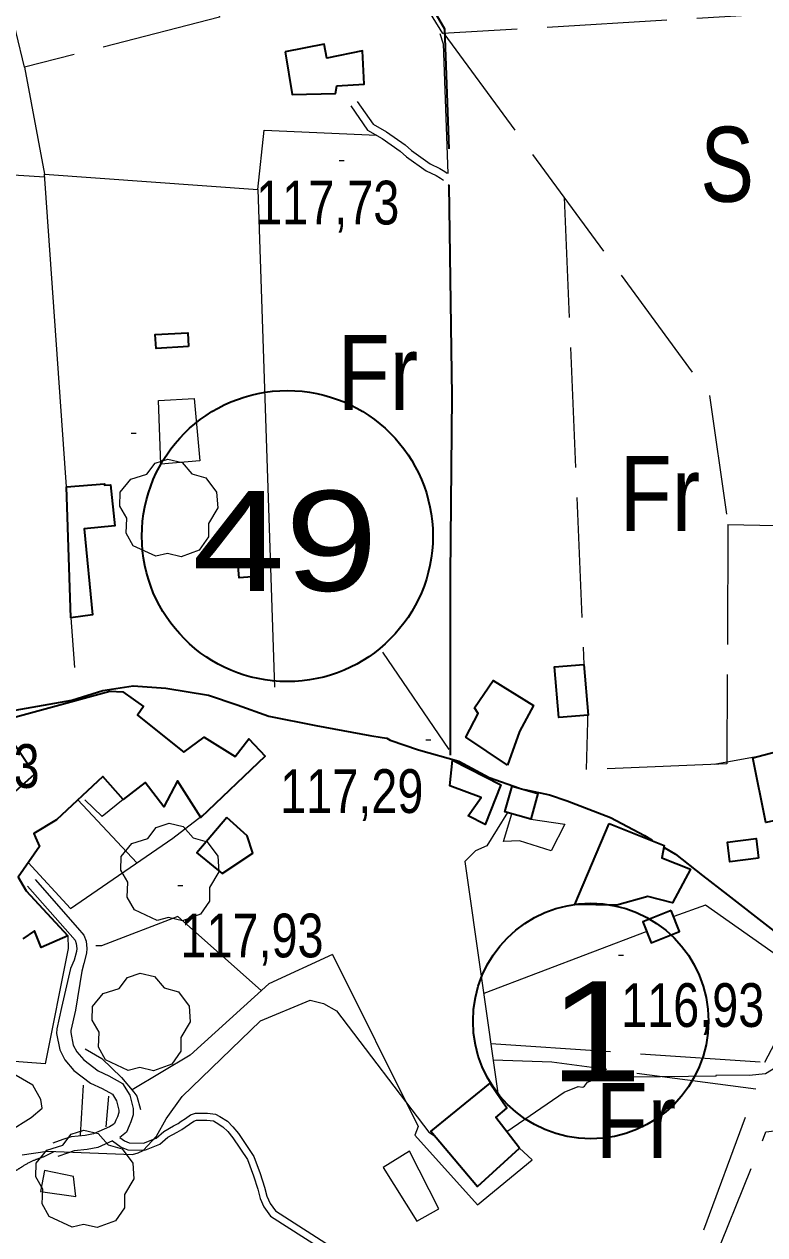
# Model space of a CAD drawing. Extents: x 483840 to 488445, y 4386047 to 4389027.
# Drawn here: x 486641.4 to 486789.5, y 4387167.2 to 4387409.3 of the extents above; entities that cross this region are included whole.
import ezdxf
from ezdxf.enums import TextEntityAlignment as Align

# ---------------------------------------------------------------- set-up
doc = ezdxf.new("R2010")
doc.units = 0
doc.header["$LTSCALE"] = 4
doc.linetypes.add('LONG_DASHED', pattern=[7.5, 6, -1.5])
doc.linetypes.add('MEDIUM_DASHED', pattern=[4.5, 3, -1.5])
for name, color, linetype, lineweight in [('13', 7, 'Continuous', 25), ('21', 7, 'Continuous', 25), ('25', 7, 'LONG_DASHED', 25), ('29', 7, 'Continuous', 13), ('38', 7, 'Continuous', 25), ('47', 7, 'Continuous', 35), ('51', 7, 'Continuous', 13), ('6', 7, 'Continuous', 35), ('7', 7, 'Continuous', 13), ('9', 7, 'Continuous', 13)]:
    doc.layers.add(name, color=color, linetype=linetype, lineweight=lineweight)
doc.layers.add('31', color=7, linetype='Continuous')

msp = doc.modelspace()

# ---------------------------------------------------------------- linework, layer by layer
at = {"layer": '21'}
for points in [[(486675.39, 4387334.46), (486676.49, 4387321.98), (486668.75, 4387321.35), (486668.26, 4387334.03)], [(486742.69, 4387250.35), (486749.51, 4387249.35), (486746.8, 4387243.99), (486740.46, 4387246.03), (486737.23, 4387245.85), (486738.94, 4387251.41)], [(486713.18, 4387180.69), (486719.93, 4387169.94), (486724.32, 4387172.43), (486718.48, 4387183.99)], [(486651.25, 4387178.88), (486645.49, 4387180.08), (486644.68, 4387175.89), (486651.72, 4387174.89)]]:
    msp.add_lwpolyline(points, close=True, dxfattribs=at)
at = {"layer": '25'}
for p, q in [((486641.45, 4387400.67), (486645.49, 4387379.31)), ((486749.4, 4387374.62), (486753.34, 4387281.26)), ((486779.41, 4387261.32), (486788.5, 4387262.98))]:
    msp.add_line(p, q, dxfattribs=at)
for points in [[(486668.94, 4387470.89), (486680.46, 4387410.7), (486641.45, 4387400.67), (486622.19, 4387482.1)], [(486645.54, 4387378.72), (486599.15, 4387381.62), (486587.21, 4387477.67)], [(486814.89, 4387349.55), (486799.86, 4387411.84), (486725.13, 4387407.43), (486717.36, 4387420.22)], [(486725.29, 4387407.45), (486778.42, 4387335.08), (486782.11, 4387309.29), (486810.46, 4387308.66)], [(486688.14, 4387376.22), (486689.37, 4387388.13), (486711.93, 4387387.08)], [(486782.11, 4387309.29), (486781.95, 4387261.42), (486753.79, 4387260.25)], [(486688.81, 4387216.06), (486672.11, 4387230.88), (486656.86, 4387225.02), (486655.75, 4387225.02)], [(486703.06, 4387223.31), (486690.3, 4387217.41), (486674.56, 4387203.15), (486662.97, 4387196.2)], [(486734.71, 4387205.52), (486789.5, 4387201.73), (486798.21, 4387218.42)], [(486607.56, 4387172.52), (486626.38, 4387181.41), (486631.95, 4387182.83), (486636.04, 4387185.55), (486638.32, 4387187.92), (486642.79, 4387190.7), (486644.99, 4387192.55), (486644.72, 4387194.28), (486643.11, 4387197.15), (486639.76, 4387199.08), (486634.67, 4387200.2), (486631.88, 4387199.34), (486628.62, 4387196.91), (486625.36, 4387194.55), (486620.2, 4387190.13), (486615.21, 4387187.5), (486609.43, 4387187.35), (486607.1, 4387187.39), (486600.63, 4387186.38)], [(486725.97, 4387152.98), (486730.79, 4387147.42), (486766.93, 4387140.08), (486787.69, 4387196.36), (486746.95, 4387201.74), (486735.2, 4387202.13)], [(486609.56, 4387156.72), (486630.57, 4387160.04), (486653.72, 4387157.46), (486670.08, 4387152.42), (486684.83, 4387149.81), (486683.34, 4387124.84), (486719.13, 4387119.6), (486726.62, 4387144.56), (486749.13, 4387138.98), (486759.81, 4387135.68), (486764.23, 4387135.46), (486768.88, 4387135.32), (486777.77, 4387158.23), (486789.75, 4387187.85), (486800.8, 4387189.1)]]:
    msp.add_lwpolyline(points, dxfattribs=at)
at = {"layer": '29'}
for points in [[(486667.74, 4387302.9), (486663.2, 4387305.02), (486661.79, 4387307.56), (486661.89, 4387310.54), (486660.52, 4387312.95), (486660.56, 4387315.7), (486662.72, 4387318.3), (486665.91, 4387319.3), (486667.56, 4387321.49), (486670.13, 4387322.32), (486672.99, 4387321.67), (486674.94, 4387319.4), (486677.75, 4387318.58), (486679.88, 4387315.73), (486680.12, 4387312.6), (486678.24, 4387309.45), (486678.24, 4387306.77), (486676.42, 4387304.16), (486672.8, 4387302.82), (486670.03, 4387303.45)], [(486667.97, 4387230.11), (486663.43, 4387232.23), (486662.02, 4387234.77), (486662.12, 4387237.75), (486660.75, 4387240.16), (486660.79, 4387242.91), (486662.95, 4387245.51), (486666.14, 4387246.51), (486667.79, 4387248.7), (486670.36, 4387249.53), (486673.22, 4387248.88), (486675.17, 4387246.61), (486677.98, 4387245.79), (486680.11, 4387242.94), (486680.35, 4387239.81), (486678.47, 4387236.66), (486678.47, 4387233.98), (486676.65, 4387231.37), (486673.03, 4387230.03), (486670.26, 4387230.66)], [(486662.22, 4387200.11), (486657.68, 4387202.23), (486656.27, 4387204.77), (486656.37, 4387207.75), (486655, 4387210.16), (486655.04, 4387212.91), (486657.2, 4387215.51), (486660.39, 4387216.51), (486662.04, 4387218.7), (486664.61, 4387219.53), (486667.47, 4387218.88), (486669.42, 4387216.61), (486672.23, 4387215.79), (486674.36, 4387212.94), (486674.6, 4387209.81), (486672.72, 4387206.66), (486672.72, 4387203.98), (486670.9, 4387201.37), (486667.28, 4387200.03), (486664.51, 4387200.66)], [(486650.96, 4387168.75), (486646.42, 4387170.87), (486645.01, 4387173.41), (486645.11, 4387176.39), (486643.74, 4387178.8), (486643.78, 4387181.55), (486645.94, 4387184.15), (486649.13, 4387185.15), (486650.78, 4387187.34), (486653.35, 4387188.17), (486656.21, 4387187.52), (486658.16, 4387185.25), (486660.97, 4387184.43), (486663.1, 4387181.58), (486663.34, 4387178.45), (486661.46, 4387175.3), (486661.46, 4387172.62), (486659.64, 4387170.01), (486656.02, 4387168.67), (486653.25, 4387169.3)]]:
    msp.add_lwpolyline(points, close=True, dxfattribs=at)
at = {"layer": '38'}
for points in [[(486707.99, 4387393.86), (486711.17, 4387389.28), (486713.83, 4387387.76), (486717.57, 4387385.16), (486718.83, 4387384.02), (486722.57, 4387381.35), (486724.54, 4387380.44), (486725.51, 4387379.85), (486726.01, 4387379.51)], [(486642.09, 4387236.92), (486650.58, 4387227.28), (486651.57, 4387226.12), (486651.81, 4387225.5), (486651.92, 4387224.47), (486651.86, 4387223.91), (486651.42, 4387222.12), (486650.68, 4387220.49)], [(486643.59, 4387238.25), (486652.09, 4387228.59), (486653.31, 4387227.17), (486653.78, 4387225.98), (486653.93, 4387224.47), (486653.83, 4387223.56), (486653.32, 4387221.46), (486652.92, 4387219.98)], [(486650.68, 4387220.49), (486648.89, 4387212.68), (486647.91, 4387208.41), (486647.89, 4387207.46), (486648.5, 4387204.21), (486649.54, 4387202.24), (486651.35, 4387200.12), (486654.68, 4387197.59), (486657.01, 4387196.47), (486659.06, 4387195.34), (486659.88, 4387194.05), (486660.35, 4387192.16), (486660.35, 4387191.71), (486660.04, 4387190.83), (486659.74, 4387190.13), (486659.48, 4387189.51), (486659.13, 4387189.21), (486658.46, 4387188.85), (486655.24, 4387187.41), (486653.57, 4387187.1), (486650.78, 4387186.83), (486649.11, 4387186.27), (486647.13, 4387185.55)], [(486652.92, 4387219.98), (486651.69, 4387212.13), (486650.75, 4387208.06), (486650.75, 4387207.7), (486651.22, 4387205.16), (486651.91, 4387203.85), (486653.31, 4387202.21), (486656.18, 4387200.03), (486658.31, 4387199), (486661.08, 4387197.48), (486662.53, 4387195.19), (486663.21, 4387192.49), (486663.19, 4387191.21), (486662.7, 4387189.8), (486662.36, 4387189.01), (486661.84, 4387187.78), (486660.55, 4387186.67)], [(486660.55, 4387186.67), (486661.47, 4387186.02), (486662.42, 4387185.62), (486665.26, 4387185.59), (486667.78, 4387186.59), (486669.33, 4387187.89), (486671.27, 4387189.02), (486672.17, 4387189.52), (486672.82, 4387189.94), (486673.65, 4387190.52), (486674.63, 4387191.23), (486675.64, 4387191.59), (486678.03, 4387191.55), (486679.66, 4387191.37), (486680.54, 4387190.91), (486682.03, 4387189.94), (486683.13, 4387188.82), (486684.26, 4387187.48), (486687.34, 4387182.92), (486688.59, 4387179.52), (486689.47, 4387176.78), (486689.95, 4387174.93), (486690.57, 4387173.52), (486691.64, 4387172), (486703.59, 4387164.38)], [(486659.05, 4387186), (486656.1, 4387184.68), (486653.97, 4387184.28), (486651.38, 4387184.03), (486650.06, 4387183.59), (486648.12, 4387182.87)]]:
    msp.add_lwpolyline(points, dxfattribs=at)
at = {"layer": '38', "linetype": 'MEDIUM_DASHED'}
for points in [[(486706.69, 4387392.96), (486710.07, 4387388.09), (486712.98, 4387386.42), (486716.58, 4387383.92), (486717.83, 4387382.78), (486721.77, 4387379.97), (486723.8, 4387379.03), (486724.65, 4387378.52), (486725.24, 4387378.11)], [(486659.05, 4387186), (486660.79, 4387184.78), (486662.12, 4387184.22), (486665.52, 4387184.18), (486668.51, 4387185.36), (486670.14, 4387186.73), (486671.97, 4387187.79), (486672.89, 4387188.31), (486673.61, 4387188.77), (486674.47, 4387189.38), (486675.29, 4387189.97), (486675.87, 4387190.18), (486677.94, 4387190.15), (486679.24, 4387190), (486679.82, 4387189.7), (486681.13, 4387188.85), (486682.09, 4387187.87), (486683.14, 4387186.62), (486686.08, 4387182.27), (486687.26, 4387179.06), (486688.12, 4387176.39), (486688.62, 4387174.47), (486689.34, 4387172.83), (486690.64, 4387170.96), (486702.83, 4387163.19)]]:
    msp.add_lwpolyline(points, dxfattribs=at)
at = {"layer": '38', "linetype": 'LONG_DASHED'}
msp.add_spline([(486607.2, 4387168.1), (486614.36, 4387170.4), (486621.75, 4387173.07), (486631.7, 4387176.15), (486637.52, 4387178.85), (486639.86, 4387180.16), (486641.15, 4387180.97), (486643.34, 4387182.14), (486645.23, 4387182.86), (486647.41, 4387183.91)], degree=3, dxfattribs=at)
at = {"layer": '47'}
for points in [[(486693.57, 4387403.76), (486695.02, 4387395.26), (486703.65, 4387395.43), (486703.9, 4387397), (486709.38, 4387397.3), (486709.03, 4387403.98), (486701.95, 4387402.51), (486701.39, 4387405.29)], [(486674.26, 4387344.83), (486667.77, 4387344.47), (486667.62, 4387347.25), (486674.11, 4387347.61)], [(486650.75, 4387290.61), (486649.85, 4387316.81), (486657.48, 4387317.36), (486657.49, 4387317.1), (486658.65, 4387317.22), (486659.5, 4387308.99), (486653.39, 4387308.4), (486655.04, 4387291.23)], [(486688.69, 4387298.92), (486684.37, 4387298.62), (486684.15, 4387301.69), (486688.47, 4387301.99)], [(486753.34, 4387281.26), (486754.19, 4387271.17), (486748.31, 4387270.68), (486747.46, 4387280.77)], [(486738.05, 4387261.15), (486729.72, 4387266.75), (486732.19, 4387271.44), (486731.46, 4387272.57), (486735.21, 4387278.07), (486743.24, 4387273.08), (486740.47, 4387267.87)], [(486806.59, 4387253.19), (486789.73, 4387249.68), (486787.14, 4387262.62), (486795.2, 4387264.76), (486809.98, 4387264.77), (486817.05, 4387266.02), (486818.71, 4387255.57), (486813.04, 4387252.65), (486814.34, 4387244.15), (486807.73, 4387243.57)], [(486727.03, 4387262.13), (486736.71, 4387257.19), (486733.6, 4387249.28), (486730.17, 4387250.98), (486732.78, 4387254.7), (486726.51, 4387257.04)], [(486742.69, 4387250.35), (486737.52, 4387251.81), (486738.96, 4387256.93), (486744.13, 4387255.47)], [(486681.92, 4387250.7), (486675.89, 4387243.58), (486681.01, 4387239.46), (486687.14, 4387243.57), (486685.99, 4387247.04)], [(486758.36, 4387249.45), (486769.41, 4387245.09), (486768.92, 4387242.62), (486774.67, 4387240.36), (486771.04, 4387233.59), (486766.11, 4387234.86), (486759.93, 4387233.15), (486751.53, 4387233.27)], [(486788.28, 4387242.57), (486782.54, 4387241.81), (486782.02, 4387245.74), (486787.76, 4387246.5)], [(486770.8, 4387232.09), (486765.12, 4387229.83), (486766.8, 4387225.62), (486772.48, 4387227.88)], [(486740.48, 4387184.58), (486735.69, 4387190.72), (486737.89, 4387192.57), (486734.51, 4387197.57), (486722.74, 4387187.98), (486732.04, 4387176.89)]]:
    msp.add_lwpolyline(points, close=True, dxfattribs=at)
for points in [[(486633.33, 4387269.1), (486658.49, 4387275.95), (486661.12, 4387275.83), (486665.28, 4387272.85), (486664.05, 4387271.14), (486673.33, 4387263.73), (486677.42, 4387266.74), (486683.6, 4387262.9), (486686.35, 4387266.39), (486689.6, 4387262.97), (486676.74, 4387250.7), (486672.05, 4387258.04), (486669.34, 4387252.83), (486665.59, 4387257.68), (486661.19, 4387254.3), (486657.12, 4387258.86), (486647.85, 4387250.21), (486643.31, 4387247.5), (486643.67, 4387246.67), (486644.47, 4387244.86), (486640.18, 4387238.76), (486641.79, 4387236.04), (486650.14, 4387226.99), (486644.78, 4387224.67), (486643.48, 4387227.99), (486641.13, 4387226.44)], [(486630.55, 4387247.83), (486643.47, 4387259.35), (486639.43, 4387265.26)]]:
    msp.add_lwpolyline(points, dxfattribs=at)
at = {"layer": '51'}
for p, q in [((486650.75, 4387290.61), (486651.43, 4387280.7)), ((486754.1, 4387272.3), (486753.79, 4387260.25)), ((486652.14, 4387254.22), (486663.95, 4387241.62)), ((486765.91, 4387227.87), (486733.29, 4387215.46)), ((486653.16, 4387197.16), (486652.57, 4387187.19)), ((486658.24, 4387194.98), (486657.75, 4387188.84))]:
    msp.add_line(p, q, dxfattribs=at)
for points in [[(486724.53, 4387407.44), (486725.18, 4387405.4), (486726.09, 4387379.44)], [(486649.85, 4387316.81), (486645.49, 4387379.31), (486688.14, 4387376.22), (486691.45, 4387276.75)], [(486661.19, 4387254.3), (486657.01, 4387250.9), (486653.53, 4387254.18)], [(486642.22, 4387241.66), (486650.67, 4387232.46), (486671.13, 4387246.57), (486677.76, 4387251.67)], [(486738.02, 4387251.67), (486733.91, 4387245), (486731.65, 4387243.98), (486729.52, 4387241.91), (486736.2, 4387195.08)], [(486798.37, 4387218.56), (486777.64, 4387233.12), (486771.29, 4387230.89)], [(486650.14, 4387226.99), (486650.18, 4387224.51), (486645.57, 4387201.39), (486637.63, 4387202.03)], [(486703.06, 4387223.31), (486720.2, 4387188.92), (486719.5, 4387187.13), (486732.06, 4387173.22), (486742.99, 4387182.21), (486740.48, 4387184.58)], [(486653.57, 4387204.43), (486656.92, 4387202.51), (486660.84, 4387198.7), (486663.35, 4387195.74), (486663.94, 4387194.98), (486664.65, 4387192.27)]]:
    msp.add_lwpolyline(points, dxfattribs=at)
at = {"layer": '6', "lineweight": 25}
msp.add_line((486713.06, 4387283.75), (486726.29, 4387264.29), dxfattribs=at)
at = {"layer": '6', "linetype": 'LONG_DASHED'}
msp.add_lwpolyline([(486710.68, 4387460.5), (486712.57, 4387448.03), (486718.24, 4387420.84), (486725.43, 4387408.38), (486726.56, 4387378.54)], dxfattribs=at)
at = {"layer": '6'}
for points in [[(486726.16, 4387377.24), (486726.32, 4387377.08), (486726.91, 4387334.91), (486726.62, 4387299.12), (486726.56, 4387263.13)], [(486628.9, 4387272.11), (486638.48, 4387271.93), (486650.95, 4387274.12), (486657.1, 4387276.06), (486663.18, 4387277.02), (486669.74, 4387276.52), (486678.26, 4387275.12), (486683.99, 4387273.21), (486690.31, 4387270.94), (486699.7, 4387269.09), (486710.54, 4387267.04), (486713.02, 4387266.69), (486713.92, 4387266.53), (486714.59, 4387266.16), (486720.23, 4387264.18), (486728.33, 4387261.91), (486734.39, 4387258.65), (486740.44, 4387256.54)], [(486741.42, 4387256.25), (486746.47, 4387255.19), (486749.97, 4387254.04), (486758.67, 4387250.65), (486765.42, 4387247.08), (486766.97, 4387246.15)], [(486769.4, 4387244.7), (486771.63, 4387243.37), (486777.04, 4387239.11), (486782.02, 4387235.2), (486805.26, 4387217.13), (486815.26, 4387207.87)]]:
    msp.add_lwpolyline(points, dxfattribs=at)
for centre, radius in [((486694.03, 4387306.95), 29.1), ((486754.71, 4387209.97), 23.55)]:
    msp.add_circle(centre, radius, dxfattribs=at)
at = {"layer": '7'}
for p, q in [((486704.39, 4387382.06), (486705.39, 4387382.06)), ((486662.78, 4387327.52), (486663.78, 4387327.52)), ((486721.73, 4387266.23), (486722.73, 4387266.23)), ((486672.14, 4387237.08), (486673.14, 4387237.08)), ((486760.28, 4387223.17), (486761.28, 4387223.17))]:
    msp.add_line(p, q, dxfattribs=at)
at = {"layer": '9'}
for points in [[(486779.88, 4387199.25), (486786.37, 4387199.13), (486789.64, 4387199.49), (486791.7, 4387200.76), (486792.39, 4387201.43), (486799.42, 4387210.31), (486800.93, 4387211.81), (486803.21, 4387213.18), (486804.05, 4387214.31), (486803.87, 4387214.84), (486803.52, 4387215.47), (486800.78, 4387218.55), (486798.89, 4387221.3), (486799.07, 4387221.72), (486799.57, 4387222.01), (486803.9, 4387221.81), (486816.22, 4387218.81), (486817.3, 4387218.8), (486819.31, 4387219.27), (486822.76, 4387219.41), (486824.2, 4387219.23), (486830.51, 4387217.76), (486830.52, 4387217.76)], [(486640.98, 4387183.24), (486646.02, 4387183.96), (486663.06, 4387183.29), (486664.19, 4387183.63), (486665.2, 4387184.11), (486667.86, 4387186.95), (486669.79, 4387190.43), (486672.96, 4387194.92), (486688.63, 4387210.04), (486698.58, 4387214.17), (486701.25, 4387213.48), (486703.88, 4387212), (486722.34, 4387187.73), (486723.66, 4387186.88)], [(486737.89, 4387187.9), (486749.37, 4387195.76), (486752.18, 4387196.88), (486753.06, 4387196.75), (486753.27, 4387196.82), (486753.46, 4387196.94), (486754.03, 4387197.76), (486756.33, 4387198.63), (486757.61, 4387198.78), (486779.79, 4387199.03), (486779.88, 4387199.25)]]:
    msp.add_lwpolyline(points, dxfattribs=at)

# ---------------------------------------------------------------- texts
at = {"layer": '13', "width": 1.25}
msp.add_text('49', height=20, dxfattribs=at).set_placement((486693.55, 4387295.99), align=Align.CENTER)
at = {"layer": '31'}
for s, width, p in [('S', 0.8, (486781.98, 4387373.79)), ('Fr', 0.85, (486712.14, 4387332.13)), ('Fr', 0.85, (486768.55, 4387307.95)), ('Fr', 0.85, (486763.74, 4387182.58))]:
    msp.add_text(s, height=15, dxfattribs=dict(at, width=width)).set_placement(p, align=Align.CENTER)
at = {"layer": '6', "width": 1.25}
msp.add_text('1', height=20, dxfattribs=at).set_placement((486755.68, 4387197.92), align=Align.CENTER)
at = {"layer": '7', "width": 0.8}
for s, p in [('117,73', (486687.79, 4387369.25)), ('117,53', (486615.84, 4387256.59)), ('117,29', (486692.6, 4387251.58)), ('117,93', (486672.64, 4387222.71)), ('116,93', (486760.78, 4387208.8))]:
    msp.add_text(s, height=8.75, dxfattribs=at).set_placement(p)

doc.saveas('drawing.dxf')
